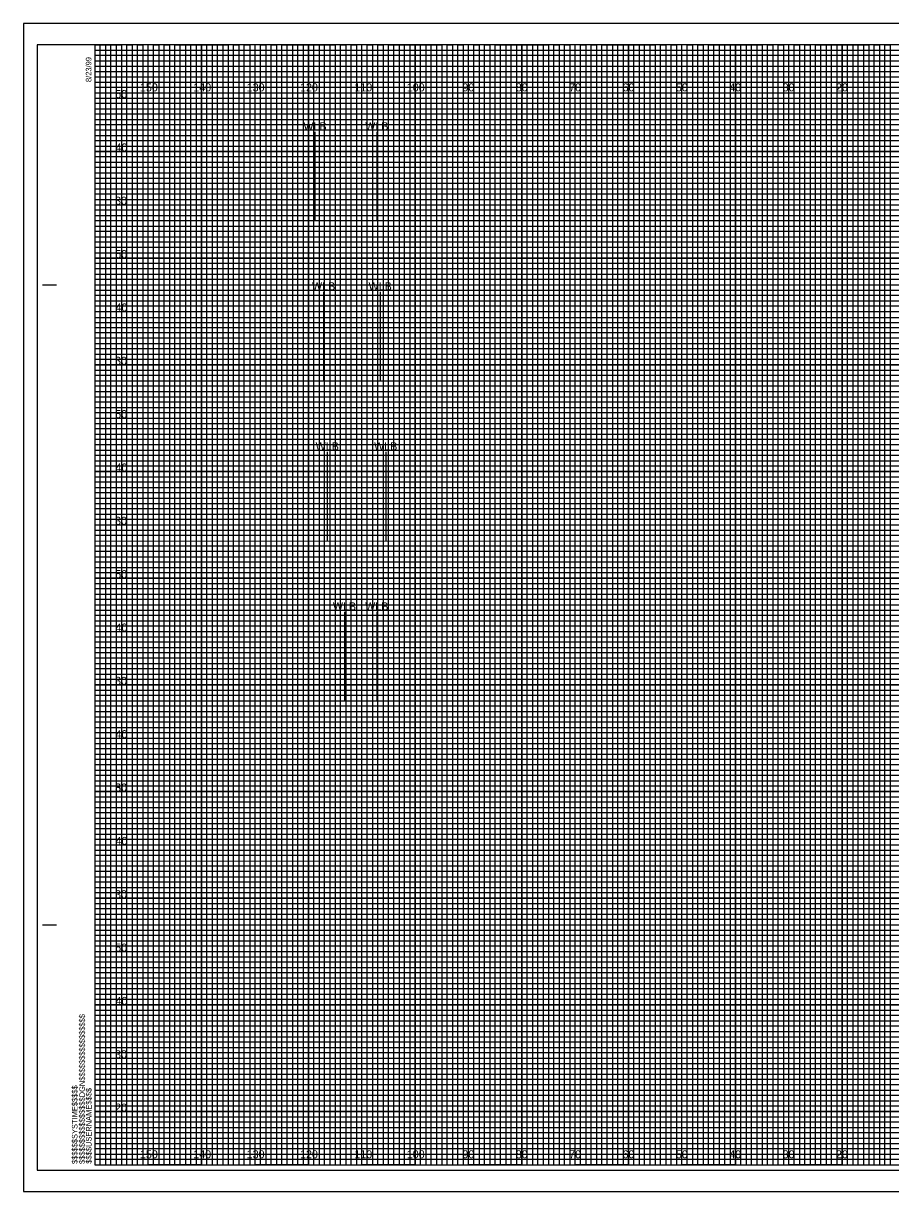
# Model space of a CAD drawing. Extents: x -13 to 323, y -5 to 214.
# Drawn here: x -13.4 to 149.1, y -5 to 214 of the extents above; entities that cross this region are included whole.
import ezdxf

# ---------------------------------------------------------------- set-up
doc = ezdxf.new("R2010")
doc.units = 0
for name, color, linetype in [('Default', 7, 'Continuous'), ('Exist Cross Section Cell', 7, 'Continuous'), ('Exist XS Center Line Elevation Label', 7, 'Continuous'), ('Exist XS Ground Line', 7, 'Continuous'), ('Prop CMT Pvmt Course 1', 7, 'Continuous'), ('Prop CMT Pvmt Course 2', 7, 'Continuous'), ('Prop CMT Pvmt Course 3', 7, 'Continuous'), ('Prop CMT Shld Paved Course 1', 7, 'Continuous'), ('Prop CMT Shld Paved Course 3', 7, 'Continuous'), ('Prop CMT Slope Grass', 7, 'Continuous'), ('Prop CMT Subgrade Earthwork', 7, 'Continuous'), ('Scratch_Level_0', 7, 'Continuous')]:
    doc.layers.add(name, color=color, linetype=linetype)

msp = doc.modelspace()

# ---------------------------------------------------------------- linework, layer by layer
at = {"layer": 'Default'}
for p, q in [((41.3, 176.93), (41.3, 193.67)), ((52.87, 176.93), (52.87, 193.67)), ((42.9, 146.93), (42.9, 163.67)), ((53.51, 146.93), (53.51, 163.67)), ((43.58, 116.93), (43.58, 133.67)), ((54.55, 116.93), (54.55, 133.67)), ((46.82, 86.93), (46.82, 103.67)), ((52.87, 86.93), (52.87, 103.67))]:
    msp.add_line(p, q, dxfattribs=at)
at = {"layer": 'Exist XS Center Line Elevation Label'}
for points in [[(0, 210), (5, 210), (5, 0), (15, 0), (15, 210), (25, 210), (25, 0), (35, 0), (35, 210), (45, 210), (45, 0), (55, 0), (55, 210), (65, 210), (65, 0), (75, 0), (75, 210), (85, 210), (85, 0), (95, 0), (95, 210), (105, 210), (105, 0), (115, 0), (115, 210), (125, 210), (125, 0), (135, 0), (135, 210), (145, 210), (145, 0), (155, 0)], [(0, 205), (275, 205)], [(0, 185), (320, 185), (320, 195), (0, 195)], [(0, 165), (320, 165), (320, 175), (0, 175)], [(0, 145), (320, 145), (320, 155), (0, 155)], [(0, 125), (320, 125), (320, 135), (0, 135)], [(0, 105), (320, 105), (320, 115), (0, 115)], [(0, 85), (320, 85), (320, 95), (0, 95)], [(0, 65), (320, 65), (320, 75), (0, 75)], [(0, 45), (320, 45), (320, 55), (0, 55)], [(0, 25), (320, 25), (320, 35), (0, 35)], [(0, 5), (320, 5), (320, 15), (0, 15)]]:
    msp.add_lwpolyline(points, dxfattribs=at)
at = {"layer": 'Exist XS Ground Line'}
for p, q in [((10, 210), (0, 210)), ((10, 0), (10, 210)), ((30, 210), (20, 210)), ((20, 210), (20, 0)), ((30, 0), (30, 210)), ((50, 210), (40, 210)), ((40, 210), (40, 0)), ((50, 0), (50, 210)), ((70, 210), (60, 210)), ((60, 210), (60, 0)), ((70, 0), (70, 210)), ((90, 210), (80, 210)), ((80, 210), (80, 0)), ((90, 0), (90, 210)), ((110, 210), (100, 210)), ((100, 210), (100, 0)), ((110, 0), (110, 210)), ((130, 210), (120, 210)), ((120, 210), (120, 0)), ((130, 0), (130, 210)), ((150, 210), (140, 210)), ((140, 210), (140, 0)), ((20, 0), (10, 0)), ((40, 0), (30, 0)), ((60, 0), (50, 0)), ((80, 0), (70, 0)), ((100, 0), (90, 0)), ((120, 0), (110, 0)), ((140, 0), (130, 0))]:
    msp.add_line(p, q, dxfattribs=at)
for points in [[(0, 200), (320, 200), (320, 190), (0, 190)], [(0, 180), (320, 180), (320, 170), (0, 170)], [(0, 160), (320, 160), (320, 150), (0, 150)], [(0, 140), (320, 140), (320, 130), (0, 130)], [(0, 120), (320, 120), (320, 110), (0, 110)], [(0, 100), (320, 100), (320, 90), (0, 90)], [(0, 80), (320, 80), (320, 70), (0, 70)], [(0, 60), (320, 60), (320, 50), (0, 50)], [(0, 40), (320, 40), (320, 30), (0, 30)], [(0, 20), (320, 20), (320, 10), (0, 10)]]:
    msp.add_lwpolyline(points, dxfattribs=at)
at = {"layer": 'Prop CMT Pvmt Course 1'}
msp.add_lwpolyline([(-10.8, -1), (322.4, -1), (322.4, 210), (-10.8, 210)], close=True, dxfattribs=at)
at = {"layer": 'Prop CMT Pvmt Course 2'}
for p, q in [((10, 0), (10, 210)), ((20, 0), (20, 210)), ((30, 0), (30, 210)), ((40, 0), (40, 210)), ((50, 0), (50, 210)), ((60, 0), (60, 210)), ((70, 0), (70, 210)), ((80, 0), (80, 210)), ((90, 0), (90, 210)), ((100, 0), (100, 210)), ((110, 0), (110, 210)), ((120, 0), (120, 210)), ((130, 0), (130, 210)), ((140, 0), (140, 210)), ((0, 200), (320, 200)), ((0, 190), (320, 190)), ((0, 180), (320, 180)), ((0, 170), (320, 170)), ((0, 160), (320, 160)), ((0, 150), (320, 150)), ((0, 140), (320, 140)), ((0, 130), (320, 130)), ((0, 120), (320, 120)), ((0, 110), (320, 110)), ((0, 100), (320, 100)), ((0, 90), (320, 90)), ((0, 80), (320, 80)), ((0, 70), (320, 70)), ((0, 60), (320, 60)), ((0, 50), (320, 50)), ((0, 40), (320, 40)), ((0, 30), (320, 30)), ((0, 20), (320, 20)), ((0, 10), (320, 10))]:
    msp.add_line(p, q, dxfattribs=at)
at = {"layer": 'Prop CMT Pvmt Course 3'}
for p, q in [((323.3, 214), (-13.4, 214)), ((-13.4, 214), (-13.4, -5)), ((-13.4, -5), (323.3, -5))]:
    msp.add_line(p, q, dxfattribs=at)
at = {"layer": 'Prop CMT Shld Paved Course 1'}
for points in [[(0, 0), (1, 0), (1, 210), (2, 210), (2, 0)], [(2, 0), (3, 0), (3, 210), (4, 210), (4, 0)], [(5, 0), (6, 0), (6, 210), (7, 210), (7, 0)], [(7, 0), (8, 0), (8, 210), (9, 210), (9, 0)], [(10, 0), (11, 0), (11, 210), (12, 210), (12, 0)], [(12, 0), (13, 0), (13, 210), (14, 210), (14, 0)], [(15, 0), (16, 0), (16, 210), (17, 210), (17, 0)], [(17, 0), (18, 0), (18, 210), (19, 210), (19, 0)], [(20, 0), (21, 0), (21, 210), (22, 210), (22, 0)], [(22, 0), (23, 0), (23, 210), (24, 210), (24, 0)], [(25, 0), (26, 0), (26, 210), (27, 210), (27, 0)], [(27, 0), (28, 0), (28, 210), (29, 210), (29, 0)], [(30, 0), (31, 0), (31, 210), (32, 210), (32, 0)], [(32, 0), (33, 0), (33, 210), (34, 210), (34, 0)], [(35, 0), (36, 0), (36, 210), (37, 210), (37, 0)], [(37, 0), (38, 0), (38, 210), (39, 210), (39, 0)], [(40, 0), (41, 0), (41, 210), (42, 210), (42, 0)], [(42, 0), (43, 0), (43, 210), (44, 210), (44, 0)], [(45, 0), (46, 0), (46, 210), (47, 210), (47, 0)], [(47, 0), (48, 0), (48, 210), (49, 210), (49, 0)], [(50, 0), (51, 0), (51, 210), (52, 210), (52, 0)], [(52, 0), (53, 0), (53, 210), (54, 210), (54, 0)], [(55, 0), (56, 0), (56, 210), (57, 210), (57, 0)], [(57, 0), (58, 0), (58, 210), (59, 210), (59, 0)], [(60, 0), (61, 0), (61, 210), (62, 210), (62, 0)], [(62, 0), (63, 0), (63, 210), (64, 210), (64, 0)], [(65, 0), (66, 0), (66, 210), (67, 210), (67, 0)], [(67, 0), (68, 0), (68, 210), (69, 210), (69, 0)], [(70, 0), (71, 0), (71, 210), (72, 210), (72, 0)], [(72, 0), (73, 0), (73, 210), (74, 210), (74, 0)], [(75, 0), (76, 0), (76, 210), (77, 210), (77, 0)], [(77, 0), (78, 0), (78, 210), (79, 210), (79, 0)], [(80, 0), (81, 0), (81, 210), (82, 210), (82, 0)], [(82, 0), (83, 0), (83, 210), (84, 210), (84, 0)], [(85, 0), (86, 0), (86, 210), (87, 210), (87, 0)], [(87, 0), (88, 0), (88, 210), (89, 210), (89, 0)], [(90, 0), (91, 0), (91, 210), (92, 210), (92, 0)], [(92, 0), (93, 0), (93, 210), (94, 210), (94, 0)], [(95, 0), (96, 0), (96, 210), (97, 210), (97, 0)], [(97, 0), (98, 0), (98, 210), (99, 210), (99, 0)], [(100, 0), (101, 0), (101, 210), (102, 210), (102, 0)], [(102, 0), (103, 0), (103, 210), (104, 210), (104, 0)], [(105, 0), (106, 0), (106, 210), (107, 210), (107, 0)], [(107, 0), (108, 0), (108, 210), (109, 210), (109, 0)], [(110, 0), (111, 0), (111, 210), (112, 210), (112, 0)], [(112, 0), (113, 0), (113, 210), (114, 210), (114, 0)], [(115, 0), (116, 0), (116, 210), (117, 210), (117, 0)], [(117, 0), (118, 0), (118, 210), (119, 210), (119, 0)], [(120, 0), (121, 0), (121, 210), (122, 210), (122, 0)], [(122, 0), (123, 0), (123, 210), (124, 210), (124, 0)], [(125, 0), (126, 0), (126, 210), (127, 210), (127, 0)], [(127, 0), (128, 0), (128, 210), (129, 210), (129, 0)], [(130, 0), (131, 0), (131, 210), (132, 210), (132, 0)], [(132, 0), (133, 0), (133, 210), (134, 210), (134, 0)], [(135, 0), (136, 0), (136, 210), (137, 210), (137, 0)], [(137, 0), (138, 0), (138, 210), (139, 210), (139, 0)], [(140, 0), (141, 0), (141, 210), (142, 210), (142, 0)], [(142, 0), (143, 0), (143, 210), (144, 210), (144, 0)], [(145, 0), (146, 0), (146, 210), (147, 210), (147, 0)], [(147, 0), (148, 0), (148, 210), (149, 210), (149, 0)]]:
    msp.add_lwpolyline(points, dxfattribs=at)
at = {"layer": 'Prop CMT Shld Paved Course 3'}
msp.add_lwpolyline([(-13.4, -5), (323.3, -5), (323.3, 214), (-13.4, 214)], close=True, dxfattribs=at)
at = {"layer": 'Prop CMT Slope Grass'}
for p, q in [((-9.8, 165), (-7.3, 165)), ((-9.7, 165), (-7.2, 165)), ((-9.8, 45), (-7.3, 45)), ((-9.7, 45), (-7.2, 45)), ((0, 0), (0, 0)), ((0, 0), (0, 0)), ((0, 0), (0, 0)), ((0, 0), (0, 0)), ((0, 0), (0, 0)), ((0, 0), (0, 0)), ((0, 0), (0, 0))]:
    msp.add_line(p, q, dxfattribs=at)
msp.add_lwpolyline([(320, 210), (0, 210), (0, 0), (320, 0)], close=True, dxfattribs=at)
at = {"layer": 'Scratch_Level_0'}
for p, q in [((0, 209), (260, 209)), ((260, 207.98), (0, 207.98)), ((0, 207.98), (0, 207)), ((0, 207), (260, 207)), ((260, 205.89), (0, 205.89)), ((0, 205.89), (0, 204)), ((0, 204), (320, 204))]:
    msp.add_line(p, q, dxfattribs=at)
for points in [[(0, 203), (270, 203), (320, 203), (320, 202), (0, 202)], [(0, 201), (320, 201), (320, 199), (0, 199)], [(0, 198), (320, 198), (320, 197), (0, 196.98)], [(0, 196), (320, 196), (320, 194), (0, 194)], [(0, 193), (320, 193), (320, 192), (0, 192)], [(0, 191), (320, 191), (320, 189), (0, 189)], [(0, 188), (320, 188), (320, 187), (0, 187)], [(0, 186), (320, 186), (320, 184), (0, 184)], [(0, 183), (320, 183), (320, 182), (0, 182)], [(0, 181), (320, 181), (320, 179), (0, 179)], [(0, 178), (320, 178), (320, 177), (0, 177)], [(0, 176), (320, 176), (320, 173.95), (320, 173), (320, 172), (0, 172)], [(0, 174), (320, 174), (320, 173), (0, 173)], [(0, 171), (320, 171), (320, 169), (0, 169.03)], [(0, 169.03), (320, 169), (320, 168), (0, 168)], [(0, 167), (320, 167), (320, 166), (0, 166)], [(0, 164), (320, 164), (320, 163), (0, 163)], [(0, 162), (320, 162), (320, 161), (0, 161)], [(-0.07, 158.89), (320, 158.89), (320, 157.88), (-0.07, 157.88)], [(0, 157), (320, 157), (320, 156), (0, 156)], [(0, 154), (320, 154), (320, 153), (0, 153)], [(0, 152), (320, 152), (320, 151), (0, 151)], [(0, 149), (320, 149), (320, 148), (0, 148)], [(0, 147), (320, 147), (320, 146), (0, 146)], [(0, 144), (320, 144), (320, 143), (0, 143)], [(0, 142), (320, 142), (320, 141), (0, 141)], [(0, 139), (320, 139), (319.99, 137.98), (0, 138)], [(0, 137), (320, 137), (320, 136), (0, 136)], [(0, 134), (320, 134), (320, 133), (0, 133)], [(0, 132), (320, 132), (320, 131), (0, 131)], [(0, 129), (320, 129), (320, 128), (0, 128)], [(0, 127), (320, 127), (320, 126), (0, 126)], [(0, 124), (320, 124), (320, 123), (0, 123)], [(0, 122), (320, 122), (320, 121), (0, 121)], [(0, 119), (320, 119), (320, 118), (0, 118)], [(0, 116.99), (320.07, 116.91), (320, 116), (0, 116)], [(0, 114), (320, 114), (320, 113), (0, 113)], [(0, 112), (320, 112), (320, 111), (0, 111)], [(0, 109), (320, 109), (320, 108), (0, 108)], [(0, 107), (320, 107), (320, 106), (0, 106)], [(0, 104), (320, 104), (320, 103), (0, 103)], [(0, 102), (320, 102), (320, 101), (0, 101)], [(0, 99), (320, 99), (320, 98), (0, 98)], [(0, 97), (320, 97), (320, 96), (0, 96)], [(0, 94), (320, 94), (320, 93), (0, 93)], [(0, 92), (320, 92), (320, 91), (0, 91)], [(0, 89), (320, 89), (320, 88), (0, 88)], [(0, 87), (320, 87), (320, 86), (0, 86)], [(0, 84), (320, 84), (320, 83), (0, 83)], [(0, 82), (320, 82), (320, 81), (0, 81)], [(0, 79), (320, 79), (319.99, 77.98), (0, 78)], [(0, 77), (320, 77), (320, 76), (0, 76)], [(0, 74), (320, 74), (320, 73), (0, 73)], [(0, 72), (320, 72), (320, 71), (0, 71)], [(0, 69), (320, 69), (320, 68), (0, 68)], [(0, 67), (320, 67), (320, 66), (0, 66)], [(0, 64), (320, 64), (320, 63), (0, 63)], [(0, 62), (320, 62), (320, 61), (0, 61)], [(0, 59), (320, 59), (320, 58), (0, 58)], [(0, 56.99), (320.07, 56.91), (320, 56), (0, 56)], [(0, 54), (320, 54), (320, 53), (0, 53)], [(0, 52), (320, 52), (320, 51), (0, 51)], [(0, 49), (320, 49), (320, 48), (0, 48)], [(0, 47), (320, 47), (320, 46), (0, 46)], [(0, 44), (320, 44), (320, 43), (0, 43)], [(0, 42), (320, 42), (320, 41), (0, 41)], [(0, 39), (320, 39), (320, 38), (0, 38)], [(0, 37), (320, 37), (320, 36), (0, 36)], [(0, 34), (320, 34), (320, 33), (0, 33)], [(0, 32), (320, 32), (320, 31), (0, 31)], [(0, 29), (320, 29), (320, 28), (0, 28)], [(0, 27), (320, 27), (320, 26), (0, 26)], [(0, 24), (320, 24), (320, 23), (0, 23)], [(0, 22), (320, 22), (320, 21), (0, 21)], [(0, 19), (320, 19), (320, 18), (0, 18)], [(0, 17), (320, 17), (320, 16), (0, 16)], [(0, 14), (320, 14), (320, 13), (0, 13)], [(0, 12), (320, 12), (320, 11), (0, 11)], [(0, 9), (320, 9), (320, 8), (0, 8)], [(0, 7), (320, 7), (320, 6), (0, 6)], [(0, 4), (320, 4), (320, 3), (0, 3)], [(0, 2), (320, 2), (320, 1), (0, 1)]]:
    msp.add_lwpolyline(points, dxfattribs=at)

# ---------------------------------------------------------------- texts
at = {"layer": 'Default'}
for p in [(39.08, 193.97), (50.65, 193.97), (40.68, 163.97), (51.28, 163.97), (41.36, 133.97), (52.32, 133.97), (44.59, 103.97), (50.64, 103.97)]:
    msp.add_text('WLB', height=1.5, dxfattribs=at).set_placement(p)
at = {"layer": 'Exist Cross Section Cell'}
for s, p in [('150', (8.44, 201.25)), ('140', (18.44, 201.25)), ('130', (28.44, 201.25)), ('120', (38.44, 201.25)), ('110', (48.62, 201.25)), ('100', (58.44, 201.25)), ('90', (68.86, 201.25)), ('80', (78.86, 201.25)), ('70', (88.86, 201.25)), ('60', (98.86, 201.25)), ('50', (108.86, 201.25)), ('40', (118.86, 201.25)), ('30', (128.86, 201.25)), ('20', (138.86, 201.25)), ('150', (8.44, 1.25)), ('140', (18.44, 1.25)), ('130', (28.44, 1.25)), ('120', (38.44, 1.25)), ('110', (48.62, 1.25)), ('100', (58.44, 1.25)), ('90', (68.86, 1.25)), ('80', (78.86, 1.25)), ('70', (88.86, 1.25)), ('60', (98.86, 1.25)), ('50', (108.86, 1.25)), ('40', (118.86, 1.25)), ('30', (128.86, 1.25)), ('20', (138.86, 1.25))]:
    msp.add_text(s, height=1.5, dxfattribs=at).set_placement(p)
at = {"layer": 'Prop CMT Slope Grass'}
for s, p in [('8/23/99', (-0.65, 203)), ('$$$$$$$$$$$$$$$$DGN$$$$$$$$$$$$$$$$', (-1.88, 0.18)), ('$$$$$$SYSTIME$$$$$', (-3.26, 0.18)), ('$$$$USERNAME$$$$', (-0.62, 0.23))]:
    msp.add_text(s, height=1.05, rotation=90, dxfattribs=at).set_placement(p)
at = {"layer": 'Prop CMT Subgrade Earthwork'}
for s, p in [('50', (3.82, 200)), ('40', (3.87, 190)), ('30', (3.78, 180)), ('50', (3.82, 170)), ('40', (3.87, 160)), ('30', (3.78, 150)), ('50', (3.82, 140)), ('40', (3.87, 130)), ('30', (3.78, 120)), ('50', (3.82, 110)), ('40', (3.87, 100)), ('30', (3.78, 90)), ('40', (3.87, 80)), ('30', (3.78, 70)), ('50', (3.82, 70)), ('40', (3.87, 60)), ('30', (3.78, 50)), ('50', (3.82, 40)), ('40', (3.87, 30)), ('30', (3.78, 20)), ('20', (3.8, 10))]:
    msp.add_text(s, height=1.5, dxfattribs=at).set_placement(p)

doc.saveas('drawing.dxf')
